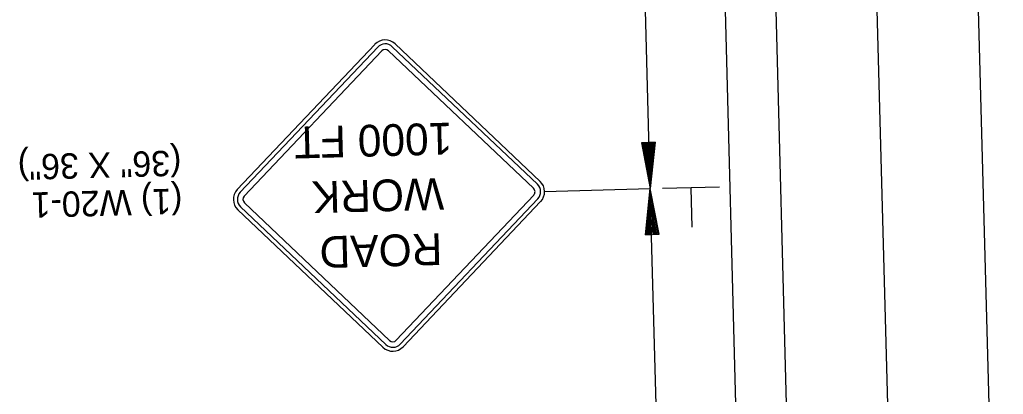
# Model space of a CAD drawing. Extents: x 1929653 to 1931621, y 596452 to 600944.
# Drawn here: x 1930634.9 to 1930867.5, y 600639.1 to 600727.6 of the extents above; entities that cross this region are included whole.
import ezdxf

# ---------------------------------------------------------------- set-up
doc = ezdxf.new("R2010")
doc.units = 0
for name, color, linetype in [('P_TC_Signs_Temporary', 7, 'Continuous'), ('R_Border', 7, 'Continuous'), ('R_Draft', 7, 'Continuous')]:
    doc.layers.add(name, color=color, linetype=linetype)

msp = doc.modelspace()

# ---------------------------------------------------------------- linework, layer by layer
at = {"layer": 'P_TC_Signs_Temporary'}
for p, q in [((1930686.39, 600687.48), (1930718.9, 600721.77)), ((1930687.07, 600686.83), (1930719.58, 600721.13)), ((1930688.03, 600685.93), (1930720.53, 600720.22)), ((1930722.12, 600720.27), (1930756.41, 600687.76)), ((1930723.02, 600721.22), (1930757.32, 600688.72)), ((1930723.67, 600721.9), (1930757.96, 600689.4)), ((1930756.46, 600686.17), (1930723.95, 600651.88)), ((1930757.41, 600685.27), (1930724.91, 600650.98)), ((1930720.82, 600650.2), (1930686.52, 600682.7)), ((1930721.46, 600650.88), (1930687.17, 600683.39)), ((1930722.36, 600651.84), (1930688.07, 600684.34)), ((1930758.09, 600684.63), (1930725.59, 600650.33))]:
    msp.add_line(p, q, dxfattribs=at)
for centre, radius, start, end in [((1930721.35, 600719.45), 3.38, 46.5377, 136.5377), ((1930721.35, 600719.45), 2.44, 46.5377, 136.5377), ((1930721.35, 600719.45), 1.13, 46.5377, 136.5377), ((1930688.84, 600685.15), 3.38, 136.5377, 226.5377), ((1930755.64, 600686.95), 1.12, 316.5377, 46.5377), ((1930755.64, 600686.95), 2.44, 316.5377, 46.5377), ((1930755.64, 600686.95), 3.38, 316.5377, 46.5377), ((1930688.84, 600685.15), 2.44, 136.5377, 226.5377), ((1930688.84, 600685.15), 1.12, 136.5377, 226.5377), ((1930723.14, 600652.65), 3.37, 226.5377, 316.5377), ((1930723.14, 600652.65), 2.44, 226.5377, 316.5377), ((1930723.14, 600652.65), 1.13, 226.5377, 316.5377)]:
    msp.add_arc(centre, radius, start, end, dxfattribs=at)
at = {"layer": 'R_Draft'}
for p, q in [((1930855.8, 600943.38), (1930867.45, 600509.53)), ((1930795.98, 600941.77), (1930807.63, 600507.92)), ((1930807.95, 600942.1), (1930819.59, 600508.24)), ((1930831.88, 600942.74), (1930843.52, 600508.89)), ((1930784.01, 600687.71), (1930781.29, 600787.67)), ((1930785.17, 600698.65), (1930781.91, 600698.51)), ((1930781.91, 600698.51), (1930784.01, 600687.71)), ((1930782.18, 600698.52), (1930783.92, 600689.53)), ((1930782.46, 600698.53), (1930783.85, 600691.39)), ((1930782.73, 600698.55), (1930783.77, 600693.2)), ((1930783.01, 600698.56), (1930783.69, 600695.05)), ((1930783.28, 600698.57), (1930783.61, 600696.86)), ((1930783.79, 600698.59), (1930783.61, 600696.86)), ((1930784.07, 600698.6), (1930783.69, 600695.05)), ((1930784.35, 600698.61), (1930783.77, 600693.2)), ((1930784.62, 600698.62), (1930783.85, 600691.39)), ((1930784.9, 600698.64), (1930783.92, 600689.53)), ((1930785.17, 600698.65), (1930784.01, 600687.71)), ((1930759.01, 600687.04), (1930784.01, 600687.71)), ((1930782.84, 600676.77), (1930784.01, 600687.71)), ((1930786.69, 600587.74), (1930784.01, 600687.71)), ((1930786.1, 600676.91), (1930784.01, 600687.71)), ((1930786.87, 600687.79), (1930800.33, 600688.15)), ((1930793.58, 600687.77), (1930793.82, 600678.58)), ((1930783.11, 600676.78), (1930784.09, 600685.89)), ((1930785.83, 600676.9), (1930784.09, 600685.89)), ((1930783.39, 600676.79), (1930784.16, 600684.03)), ((1930785.55, 600676.88), (1930784.16, 600684.03)), ((1930783.66, 600676.81), (1930784.24, 600682.21)), ((1930783.94, 600676.82), (1930784.32, 600680.37)), ((1930785.28, 600676.87), (1930784.24, 600682.21)), ((1930785, 600676.86), (1930784.32, 600680.37)), ((1930784.22, 600676.82), (1930784.4, 600678.55)), ((1930784.73, 600676.85), (1930784.4, 600678.55)), ((1930782.84, 600676.77), (1930786.1, 600676.91))]:
    msp.add_line(p, q, dxfattribs=at)

# ---------------------------------------------------------------- texts
at = {"layer": 'P_TC_Signs_Temporary'}
for s, p in [('1000 FT', (1930737.07, 600703.29)), ('WORK', (1930735.12, 600690.21)), (' ROAD ', (1930737.51, 600677.24))]:
    msp.add_text(s, height=7.5, rotation=181.5377, dxfattribs=at).set_placement(p)
at = {"layer": 'R_Border'}
for s, p in [('(36" X 36")', (1930673.1, 600696.74)), ('(1) W20-1', (1930673.34, 600687.74))]:
    msp.add_text(s, height=6, rotation=181.5377, dxfattribs=at).set_placement(p)

doc.saveas('drawing.dxf')
